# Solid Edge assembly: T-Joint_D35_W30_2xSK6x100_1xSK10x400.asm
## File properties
Author: fknapp
Template: iso metric assembly.asm
Last saved by: fknapp
Revision: 8
Application: Solid Edge
Username: fknapp
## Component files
T-Joint_D35_W30.par
SK Schraube 6x100_ohne_Gewinde.par
SK Schraube 10x400_ohne_Gewinde_22042020.par
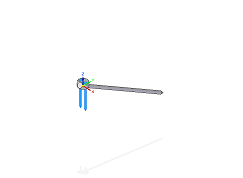
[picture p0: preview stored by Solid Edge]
